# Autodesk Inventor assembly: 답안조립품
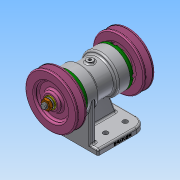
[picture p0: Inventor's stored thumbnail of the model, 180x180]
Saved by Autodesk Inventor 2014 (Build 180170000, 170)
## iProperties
Created: 2020-06
Part Number: 답안조립품
Document SubType Name: Assembly
Designer: net
Author: net
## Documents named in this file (12)
- C:\Users\net\Desktop\700606V1019\답안조립품.iam
- C:\Users\net\Desktop\700606V1019\본체.ipt
- C:\Users\net\Desktop\700606V1019\축.ipt
- C:\Users\net\Desktop\700606V1019\베어링 6204.ipt
- C:\Users\net\Desktop\700606V1019\커버.ipt
- C:\Users\net\Desktop\700606V1019\오일 실 20 32 5.ipt
- C:\Users\net\Desktop\700606V1019\키 5x5x12.ipt
- C:\Users\net\Desktop\700606V1019\볼트 M4.ipt
- C:\Users\net\Desktop\700606V1019\V-벨트풀리.ipt
- C:\Users\net\Desktop\700606V1019\평면 와셔 10x21.ipt
- C:\Users\net\Desktop\700606V1019\스프링 와셔 10.ipt
- C:\Users\net\Desktop\700606V1019\너트 M10.ipt
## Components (2 placed, 1 different names)
1. V-벨트풀리:1
2. V-벨트풀리:2
